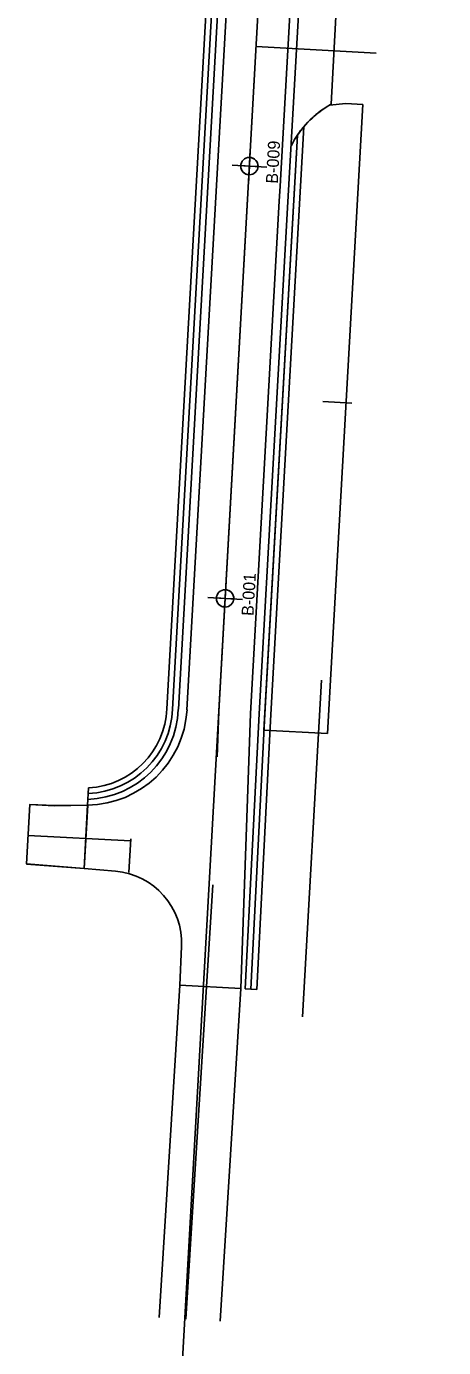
# Model space of a CAD drawing. Extents: x 1973866 to 1974130, y 734965 to 738427.
# Drawn here: x 1973866.1 to 1974010.4, y 735603.9 to 736061.7 of the extents above; entities that cross this region are included whole.
import ezdxf

# ---------------------------------------------------------------- set-up
doc = ezdxf.new("R2010")
doc.units = 0
for name, color, linetype in [('CM_Corridor_Range_Conceptual', 7, 'Continuous'), ('DR_P_Cells', 7, 'Continuous'), ('DR_P_Ditch', 7, 'Continuous'), ('DR_P_Headwall', 7, 'Continuous'), ('DR_P_Storm_Sewer', 7, 'Continuous'), ('DR_X_Cells', 7, 'Continuous'), ('DR_X_GenericNode', 7, 'Continuous'), ('DR_X_Storm_Sewer', 7, 'Continuous'), ('GE_P_Alignment', 7, 'Continuous'), ('MD_P_ACIC_B', 7, 'Continuous'), ('MD_P_Surface_Asphalt_Concrete_Base', 7, 'Continuous'), ('PV_P_Shoulder', 7, 'Continuous'), ('SC_ProfileRun2', 7, 'Continuous'), ('SC_ProfileRun3', 7, 'Continuous'), ('SC_Scratch1', 7, 'Continuous'), ('SH_Text', 7, 'Continuous')]:
    doc.layers.add(name, color=color, linetype=linetype)

msp = doc.modelspace()

# ---------------------------------------------------------------- linework, layer by layer
at = {"layer": 'CM_Corridor_Range_Conceptual'}
for p, q in [((1973914.65, 735825.29), (1973937.18, 736227.01)), ((1973950.59, 735823.27), (1973962.01, 736026.86)), ((1973945.76, 735728.04), (1973950.59, 735823.28)), ((1973887.56, 735797.89), (1973887.46, 735795.88)), ((1973943.77, 735728.15), (1973945.76, 735728.04))]:
    msp.add_line(p, q, dxfattribs=at)
msp.add_arc((1973886.12, 735826.39), 28.54, 272.8819, 357.7242, dxfattribs=at)
at = {"layer": 'DR_P_Cells'}
msp.add_line((1973884.41, 734964.92), (1974010.42, 737211.15), dxfattribs=at)
at = {"layer": 'DR_P_Ditch'}
msp.add_line((1973978.67, 735931.16), (1973968.69, 735931.72), dxfattribs=at)
at = {"layer": 'DR_P_Headwall'}
msp.add_line((1973987.09, 736052.39), (1973945.54, 736054.72), dxfattribs=at)
at = {"layer": 'DR_P_Storm_Sewer'}
for p, q in [((1973918.64, 735825.07), (1973996.44, 737211.94)), ((1973956.55, 736000.91), (1973961.41, 736087.61)), ((1973946.59, 735823.5), (1973956.55, 736000.91)), ((1973941.77, 735728.27), (1973946.59, 735823.5)), ((1973887.35, 735793.87), (1973887.25, 735791.86))]:
    msp.add_line(p, q, dxfattribs=at)
msp.add_arc((1973886.16, 735826.35), 32.5, 272.1064, 357.7326, dxfattribs=at)
at = {"layer": 'DR_X_Cells'}
for p, q in [((1973916.64, 735825.18), (1973939.07, 736224.93)), ((1973887.46, 735795.88), (1973887.35, 735793.87)), ((1973941.77, 735728.27), (1973943.77, 735728.15))]:
    msp.add_line(p, q, dxfattribs=at)
msp.add_lwpolyline([(1973943.77, 735728.15), (1973948.59, 735823.39), (1973959.85, 736024)], dxfattribs=at)
msp.add_arc((1973886.12, 735826.39), 30.54, 272.5004, 357.7242, dxfattribs=at)
at = {"layer": 'DR_X_GenericNode'}
for p, q in [((1973886.02, 735769.87), (1973887.25, 735791.86)), ((1973886.02, 735769.87), (1973866.08, 735771.45)), ((1973919.15, 735729.54), (1973912, 735614.32)), ((1973940.21, 735728.35), (1973933.06, 735613.14))]:
    msp.add_line(p, q, dxfattribs=at)
msp.add_lwpolyline([(1973867.23, 735792.1), (1973875.61, 735791.68), (1973887.25, 735791.86)], dxfattribs=at)
at = {"layer": 'DR_X_Storm_Sewer'}
for p, q in [((1973947.03, 736081.21), (1973932.62, 735824.28)), ((1973932.62, 735824.28), (1973932.08, 735808.59)), ((1973902.13, 735779.55), (1973866.64, 735781.36)), ((1973930.55, 735764.32), (1973921.21, 735613.8))]:
    msp.add_line(p, q, dxfattribs=at)
at = {"layer": 'GE_P_Alignment'}
msp.add_line((1973961.63, 735718.57), (1973968.17, 735835.18), dxfattribs=at)
at = {"layer": 'MD_P_ACIC_B'}
for centre in [(1973943.22, 736013.27), (1973934.82, 735863.51)]:
    msp.add_circle(centre, 0.05, dxfattribs=at)
at = {"layer": 'MD_P_Surface_Asphalt_Concrete_Base'}
for p, q in [((1973943.22, 736013.27), (1973943.55, 736019.26)), ((1973943.22, 736013.27), (1973943.39, 736016.27)), ((1973943.22, 736013.27), (1973937.23, 736013.61)), ((1973940.22, 736013.44), (1973943.22, 736013.27)), ((1973943.22, 736013.27), (1973942.88, 736007.28)), ((1973943.22, 736013.27), (1973943.05, 736010.27)), ((1973943.22, 736013.27), (1973949.21, 736012.93)), ((1973946.21, 736013.1), (1973943.22, 736013.27)), ((1973934.82, 735863.51), (1973935.15, 735869.5)), ((1973934.82, 735863.51), (1973928.83, 735863.84)), ((1973931.82, 735863.67), (1973934.82, 735863.51)), ((1973934.82, 735863.51), (1973934.48, 735857.51)), ((1973934.82, 735863.51), (1973934.65, 735860.51)), ((1973934.82, 735863.51), (1973934.99, 735866.5)), ((1973934.82, 735863.51), (1973940.81, 735863.17)), ((1973937.81, 735863.34), (1973934.82, 735863.51))]:
    msp.add_line(p, q, dxfattribs=at)
for centre in [(1973943.22, 736013.27), (1973934.82, 735863.51)]:
    msp.add_circle(centre, 3, dxfattribs=at)
for centre, start, end in [((1973943.22, 736013.27), 356.7892, 86.7892), ((1973943.22, 736013.27), 176.7892, 266.7892), ((1973934.82, 735863.51), 176.7892, 266.7892), ((1973934.82, 735863.51), 356.7892, 86.7892)]:
    msp.add_arc(centre, 3, start, end, dxfattribs=at)
at = {"layer": 'PV_P_Shoulder'}
for p, q in [((1973970.25, 735816.64), (1973982.47, 736034.57)), ((1973976.57, 736035.02), (1973970.92, 736034.42)), ((1973982.47, 736034.57), (1973976.57, 736035.02)), ((1973948.28, 735817.87), (1973959.85, 736024)), ((1973970.25, 735816.64), (1973948.28, 735817.87))]:
    msp.add_line(p, q, dxfattribs=at)
msp.add_arc((1973988.79, 736004.32), 35, 120.7057, 145.7865, dxfattribs=at)
msp.add_arc((1973988.79, 736004.32), 35, 120.7057, 145.7865, dxfattribs=at)
at = {"layer": 'SC_ProfileRun2'}
msp.add_line((1973902.16, 735780.18), (1973901.5, 735768.57), dxfattribs=at)
at = {"layer": 'SC_ProfileRun3'}
for p, q in [((1973887.14, 735789.86), (1973887.25, 735791.86)), ((1973938.22, 735728.47), (1973940.21, 735728.35))]:
    msp.add_line(p, q, dxfattribs=at)
at = {"layer": 'SC_Scratch1'}
for p, q in [((1973921.63, 735824.9), (1973999.43, 737211.77)), ((1973953.84, 736006.28), (1973959.21, 736101.93)), ((1973971.47, 736034.74), (1973973.54, 736071.68)), ((1973953.55, 736001.08), (1973953.84, 736006.28)), ((1973943.6, 735823.67), (1973953.55, 736001.08)), ((1973940.21, 735728.35), (1973943.6, 735823.67)), ((1973887.25, 735791.86), (1973886.02, 735769.87)), ((1973886.02, 735769.87), (1973896.86, 735768.96)), ((1973919.74, 735742.95), (1973919.15, 735729.54)), ((1973940.21, 735728.35), (1973919.15, 735729.54))]:
    msp.add_line(p, q, dxfattribs=at)
for centre, radius, start, end in [((1973988.79, 736004.32), 35, 119.6676, 152.8937), ((1973886.69, 735826.86), 35, 270.9216, 356.7892), ((1973894.77, 735744.05), 25, 357.4825, 85.1966)]:
    msp.add_arc(centre, radius, start, end, dxfattribs=at)
at = {"layer": 'SH_Text'}
msp.add_lwpolyline([(1973886.02, 735769.92), (1973866.13, 735771.5), (1973867.29, 735792.14), (1973875.66, 735791.72), (1973887.35, 735791.91)], close=True, dxfattribs=at)

# ---------------------------------------------------------------- texts
at = {"layer": 'SC_Scratch1'}
for s, p in [('B-009', (1973953.06, 736007.12)), ('B-001', (1973944.65, 735857.36))]:
    msp.add_text(s, height=4.167, rotation=86.7892, dxfattribs=at).set_placement(p)

doc.saveas('drawing.dxf')
